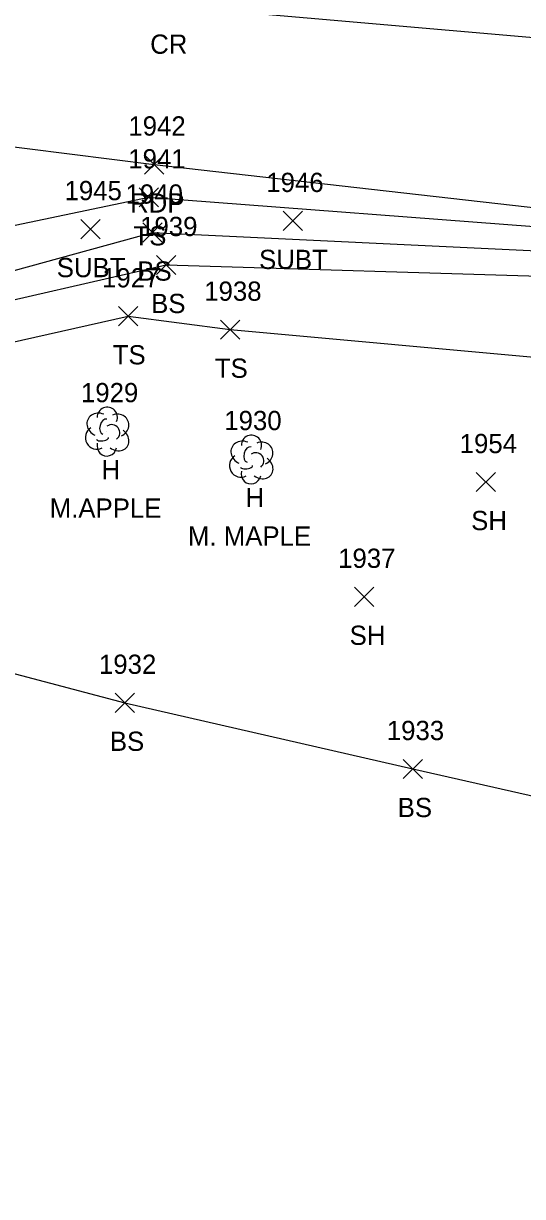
# Model space of a CAD drawing. Extents: x 1462089 to 1464015, y 730534 to 736144.
# Drawn here: x 1462970.7 to 1463022.5, y 734883 to 735004.8 of the extents above; entities that cross this region are included whole.
import ezdxf

# ---------------------------------------------------------------- set-up
doc = ezdxf.new("R2010")
doc.units = 0
for name, color, linetype in [('L_A', 7, 'Continuous'), ('L_C', 7, 'Continuous'), ('L_I', 7, 'Continuous'), ('L_TIC', 7, 'Continuous'), ('LELB', 7, 'Continuous'), ('LTD', 7, 'Continuous'), ('P_A', 7, 'Continuous'), ('P_I', 7, 'Continuous'), ('P_TIC', 7, 'Continuous'), ('PET', 7, 'Continuous'), ('PRC', 7, 'Continuous'), ('U_A', 7, 'Continuous'), ('U_I', 7, 'Continuous'), ('U_TIC', 7, 'Continuous')]:
    doc.layers.add(name, color=color, linetype=linetype)

msp = doc.modelspace()

# ---------------------------------------------------------------- linework, layer by layer
at = {"layer": 'L_TIC'}
for points in [[(1462982.7, 734985.78), (1462984.7, 734987.78)], [(1462984.7, 734985.78), (1462982.7, 734987.78)], [(1462983.07, 734982.12), (1462985.07, 734984.12)], [(1462985.07, 734982.12), (1462983.07, 734984.12)], [(1462984.5, 734978.75), (1462986.5, 734980.75)], [(1462986.5, 734978.75), (1462984.5, 734980.75)], [(1462980.55, 734973.42), (1462982.55, 734975.42)], [(1462982.55, 734973.42), (1462980.55, 734975.42)], [(1462991.14, 734972.03), (1462993.14, 734974.03)], [(1462993.14, 734972.03), (1462991.14, 734974.03)], [(1463017.65, 734956.2), (1463019.65, 734958.2)], [(1463019.65, 734956.2), (1463017.65, 734958.2)], [(1463005.04, 734944.28), (1463007.04, 734946.28)], [(1463007.04, 734944.28), (1463005.04, 734946.28)], [(1462980.22, 734933.27), (1462982.22, 734935.27)], [(1462982.22, 734933.27), (1462980.22, 734935.27)], [(1463010.08, 734926.39), (1463012.08, 734928.39)], [(1463012.08, 734926.39), (1463010.08, 734928.39)]]:
    msp.add_lwpolyline(points, dxfattribs=at)
at = {"layer": 'LELB'}
for points in [[(1462941.98, 734938.95), (1462935.31, 734946.73), (1462934.38, 734953.64), (1462936.03, 734961.3), (1462944.88, 734969.88), (1462943.68, 734973.85), (1462943.92, 734974.01), (1462950.44, 734978.44), (1462964.03, 734982.68), (1462983.7, 734986.78), (1463027.31, 734983.46), (1463060.68, 734977.02)], [(1462938.67, 734953.95), (1462941.73, 734957.97), (1462950.38, 734969.98), (1462948.06, 734970.93), (1462946.19, 734971.05), (1462945.99, 734972.43), (1462947.05, 734973.46), (1462952.27, 734976.04), (1462964.78, 734977.82), (1462984.07, 734983.12), (1463026.89, 734981.09), (1463060.68, 734977.02)], [(1462938.67, 734953.95), (1462939.85, 734951.97), (1462941.31, 734953.17), (1462944.34, 734955.18), (1462951.57, 734966.42), (1462954.81, 734972.92), (1462963.16, 734974.65), (1462985.5, 734979.75), (1463026.56, 734978.52), (1463063.17, 734972.33)], [(1462941.98, 734938.95), (1462946.63, 734945.19), (1462948.63, 734946.33), (1462954.69, 734963.9), (1462962.17, 734970.07), (1462981.55, 734974.42), (1462992.14, 734973.03), (1463025.97, 734969.98), (1463056.78, 734946.93), (1463060.24, 734962.86), (1463062.89, 734971.59), (1463070.92, 734967.51), (1463063.42, 734958.41)], [(1462960.9, 734939.64), (1462981.22, 734934.27), (1463011.08, 734927.39), (1463044.4, 734919.87), (1463076.48, 734907.5), (1463096.48, 734914.14), (1463113.34, 734909.53), (1463132.2, 734900.42), (1463146.06, 734873.76), (1463140.01, 734844.07), (1463136.33, 734794.96), (1463139.65, 734759.84), (1463135.97, 734722.82), (1463137.81, 734685.14), (1463138.61, 734654.4)]]:
    msp.add_lwpolyline(points, dxfattribs=at)
at = {"layer": 'LTD'}
for p, q in [((1462979.36, 734962.49), (1462979.36, 734962.49)), ((1462979.36, 734962.49), (1462979.36, 734962.49)), ((1462994.31, 734959.59), (1462994.31, 734959.59)), ((1462994.31, 734959.59), (1462994.31, 734959.59))]:
    msp.add_line(p, q, dxfattribs=at)
for centre in [(1462979.4, 734963.93), (1462994.35, 734961.02)]:
    msp.add_arc(centre, 1.05, 335.5272, 180.9563, dxfattribs=at)
for centre, major_axis, ratio, start_param, end_param in [((1462978.57, 734963.16), (1.21, -0.51), 0.895232, 1.570796, 4.712389), ((1462979.15, 734962.95), (-0.208, -0.792), 0.645439, 3.141593, 6.283185), ((1462980.4, 734963.08), (-1.14, -0.48), 0.949671, 1.570796, 4.712389), ((1462978.27, 734961.79), (0.58, -1.04), 0.959034, 3.141593, 6.283185), ((1462979.86, 734962.33), (-0.5, 0.667), 0.989748, 3.141593, 6.283185), ((1462980.36, 734961.66), (-1.09, 0.79), 0.841452, 1.570796, 4.712389), ((1462978.9, 734961.74), (-0.625, -0.083), 0.423636, 0, 3.141593), ((1462993.51, 734960.25), (1.21, -0.51), 0.895232, 1.570796, 4.712389), ((1462995.35, 734960.17), (-1.14, -0.48), 0.949671, 1.570796, 4.712389), ((1462979.36, 734960.99), (0.26, 1.06), 0.942809, 1.570796, 4.712389), ((1462994.1, 734960.05), (-0.208, -0.792), 0.645439, 3.141593, 6.283185), ((1462994.81, 734959.42), (-0.5, 0.667), 0.989748, 3.141593, 6.283185), ((1462993.22, 734958.88), (0.58, -1.04), 0.959034, 3.141593, 6.283185), ((1462993.85, 734958.84), (-0.625, -0.083), 0.423636, 0, 3.141593), ((1462995.31, 734958.75), (-1.09, 0.79), 0.841452, 1.570796, 4.712389), ((1462994.31, 734958.09), (0.26, 1.06), 0.942809, 1.570796, 4.712389)]:
    msp.add_ellipse(centre, major_axis=major_axis, ratio=ratio, start_param=start_param, end_param=end_param, dxfattribs=at)
at = {"layer": 'P_TIC'}
for points in [[(1462983.27, 734989.19), (1462985.27, 734991.19)], [(1462985.27, 734989.19), (1462983.27, 734991.19)]]:
    msp.add_lwpolyline(points, dxfattribs=at)
at = {"layer": 'PET'}
msp.add_lwpolyline([(1462887.99, 735000.18), (1462896.99, 734999.73), (1462921.5, 734997.41), (1462942.8, 734994.69), (1462953.49, 734994.05), (1462984.27, 734990.19), (1463026.29, 734985.41), (1463062.31, 734980.2), (1463112.76, 734970.65), (1463141.53, 734965.09), (1463163.13, 734960.72), (1463175.95, 734956.7), (1463185.66, 734949.18), (1463198.51, 734929.67)], dxfattribs=at)
at = {"layer": 'PRC'}
msp.add_lwpolyline([(1462893.86, 735015.03), (1462924.16, 735012.51), (1462985.41, 735006.69), (1463029.58, 735002.86), (1463065.18, 734999.27), (1463115.87, 734995.03), (1463143.92, 734993.12), (1463182.72, 734989.92), (1463197.75, 734989.04)], dxfattribs=at)
at = {"layer": 'U_TIC'}
for points in [[(1462976.65, 734982.48), (1462978.65, 734984.48)], [(1462978.65, 734982.48), (1462976.65, 734984.48)], [(1462997.64, 734983.33), (1462999.64, 734985.33)], [(1462999.64, 734983.33), (1462997.64, 734985.33)]]:
    msp.add_lwpolyline(points, dxfattribs=at)

# ---------------------------------------------------------------- texts
at = {"layer": 'L_A'}
for s, p in [('TS', (1462982.11, 734981.78)), ('BS', (1462982.51, 734978.12)), ('BS', (1462983.94, 734974.75)), ('TS', (1462979.96, 734969.42)), ('TS', (1462990.55, 734968.03)), ('H', (1462978.79, 734957.49)), ('H', (1462993.74, 734954.59)), ('SH', (1463017.14, 734952.2)), ('SH', (1463004.53, 734940.28)), ('BS', (1462979.66, 734929.27)), ('BS', (1463009.52, 734922.39))]:
    msp.add_text(s, height=2, dxfattribs=at).set_placement(p)
at = {"layer": 'L_C'}
for s, p in [('M.APPLE', (1462973.42, 734953.49)), ('M. MAPLE', (1462987.76, 734950.59))]:
    msp.add_text(s, height=2, dxfattribs=at).set_placement(p)
at = {"layer": 'L_I'}
for s, p in [('1941', (1462981.57, 734989.78)), ('1940', (1462981.29, 734986.12)), ('1939', (1462982.8, 734982.75)), ('1927', (1462978.85, 734977.42)), ('1938', (1462989.45, 734976.03)), ('1929', (1462976.66, 734965.49)), ('1930', (1462991.53, 734962.59)), ('1954', (1463015.95, 734960.2)), ('1937', (1463003.34, 734948.28)), ('1932', (1462978.53, 734937.27)), ('1933', (1463008.39, 734930.39))]:
    msp.add_text(s, height=2, dxfattribs=at).set_placement(p)
at = {"layer": 'P_A'}
for s, p in [('CR', (1462983.84, 735001.69)), ('RDP', (1462981.76, 734985.19))]:
    msp.add_text(s, height=2, dxfattribs=at).set_placement(p)
at = {"layer": 'P_I'}
msp.add_text('1942', height=2, dxfattribs=at).set_placement((1462981.58, 734993.19))
at = {"layer": 'U_A'}
for p in [(1462995.14, 734979.33), (1462974.15, 734978.48)]:
    msp.add_text('SUBT', height=2, dxfattribs=at).set_placement(p)
at = {"layer": 'U_I'}
for s, p in [('1946', (1462995.89, 734987.33)), ('1945', (1462974.96, 734986.48))]:
    msp.add_text(s, height=2, dxfattribs=at).set_placement(p)

doc.saveas('drawing.dxf')
